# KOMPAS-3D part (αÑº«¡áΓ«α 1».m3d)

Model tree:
1. Эскиз:1
2. Операция выдавливания:36
     Толщина стенки 1 = 2; Толщина стенки 2 = 6; Расстояние 1 = 1; Расстояние 2 = 3
3. Эскиз:38
4. Операция выдавливания:40
     Толщина стенки 1 = 2; Толщина стенки 2 = 6; Расстояние 1 = 5; Расстояние 2 = 3
5. Эскиз:39
6. Операция выдавливания:41
     Толщина стенки 1 = 2; Толщина стенки 2 = 6; Расстояние 1 = 1; Расстояние 2 = 3
7. Эскиз:40
8. Операция выдавливания:42
     Толщина стенки 1 = 2; Толщина стенки 2 = 2.5; Расстояние 1 = 50; Расстояние 2 = 3
9. Эскиз:41
10. Вырезать элемент выдавливания:4
     Толщина стенки 2 = 1.5; Расстояние 1 = 40
11. Эскиз:42
12. Операция выдавливания:43
     Толщина стенки 1 = 2; Толщина стенки 2 = 2.5; Расстояние 1 = 50; Расстояние 2 = 3
13. Эскиз:43
14. Вырезать элемент выдавливания:5
     Толщина стенки 2 = 1.5; Расстояние 1 = 40
15. Эскиз:44
16. Операция выдавливания:44
     Толщина стенки 1 = 2; Толщина стенки 2 = 2.5; Расстояние 1 = 10; Расстояние 2 = 3
17. Эскиз:45
18. Эскиз:46
19. Операция выдавливания:47
     Толщина стенки 1 = 2; Толщина стенки 2 = 6; Расстояние 1 = 1; Расстояние 2 = 3
20. Эскиз:47
21. Операция выдавливания:48
     Толщина стенки 1 = 2; Толщина стенки 2 = 6; Расстояние 1 = 5; Расстояние 2 = 3
22. Эскиз:48
23. Операция выдавливания:49
     Толщина стенки 1 = 2; Толщина стенки 2 = 6; Расстояние 1 = 1; Расстояние 2 = 3
24. Эскиз:49
25. Вырезать элемент выдавливания:6
     Толщина стенки 2 = 1.5; Расстояние 1 = 22
26. Эскиз:50
27. Вырезать элемент выдавливания:7
     Толщина стенки 2 = 1.5; Расстояние 1 = 1
28. Эскиз:51
29. Вырезать элемент выдавливания:8
     Толщина стенки 2 = 1.5; Расстояние 1 = 151
30. Эскиз:52
31. Операция выдавливания:50
     Толщина стенки 1 = 2; Толщина стенки 2 = 6; Расстояние 1 = 1; Расстояние 2 = 0.5
